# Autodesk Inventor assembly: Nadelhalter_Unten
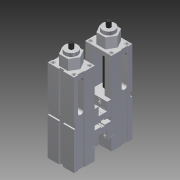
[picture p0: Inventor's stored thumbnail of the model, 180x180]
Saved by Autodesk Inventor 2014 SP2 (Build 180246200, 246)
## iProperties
Created: 2015-06
Part Number: Nadelhalter_Unten
Document SubType Name: Assembly
Designer: e_krauts
Mass: 8692.88 g
Surface Area: 10150.6 cm^2
Volume: 8677.37 cm^3
Density: 1.00179 g/cm^3
Sending System: SolidWorks 2011
Last Author: e_boekem
Author: e_krauts
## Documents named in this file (8)
- C:\Users\e_krauts\AppData\Local\SolidCAM Temporary Files\NADELHALTER_UNTEN\DesignModel.iam
- Z:\VDW-Nachwuchsstiftung Intern\Mitarbeiter Ablage\Steffen Krauth\IVCAM\Nadelhalterung.ipt
- C:\Users\e_krauts\AppData\Local\SolidCAM Temporary Files\NADELHALTER_UNTEN\Schraubstock.iam
- C:\Users\e_krauts\AppData\Local\SolidCAM Temporary Files\NADELHALTER_UNTEN\Backe20x40.ipt
- C:\Users\e_krauts\AppData\Local\SolidCAM Temporary Files\NADELHALTER_UNTEN\Unterteil.ipt
- C:\Users\e_krauts\AppData\Local\SolidCAM Temporary Files\NADELHALTER_UNTEN\Backe 40 x 20 ohne.ipt
- C:\Users\e_krauts\AppData\Local\SolidCAM Temporary Files\NADELHALTER_UNTEN\Spindel.ipt
- C:\Users\e_krauts\AppData\Local\SolidCAM Temporary Files\NADELHALTER_UNTEN\Nadelhalterung-Unterteil_01.ipt
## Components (6 placed, 6 different names)
1. Backe20x40:1 — Passend:2, Fluchtend:1, Fluchtend:3
2. Unterteil:1 — Passend:1, Passend:2, Passend:4, Passend:5, Fluchtend:1
3. Backe 40 x 20 ohne:1 — Passend:3, Passend:4, Fluchtend:4, Fluchtend:5, Passend:6, Passend:7
4. Spindel:2 — Passend:1, Passend:3, Passend:5
5. Schraubstock:1 [sub-assembly] — Fluchtend:3, Fluchtend:4
6. Nadelhalterung-Unterteil_01:1 — Fluchtend:5, Passend:6, Passend:7
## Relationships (11: Mate 7, Flush 4)
- Passend:1 [Mate]: Unterteil:1 ↔ Spindel:2
- Passend:2 [Mate]: Backe20x40:1 ↔ Unterteil:1
- Passend:3 [Mate]: Backe 40 x 20 ohne:1 ↔ Spindel:2
- Passend:4 [Mate]: Unterteil:1 ↔ Backe 40 x 20 ohne:1
- Passend:5 [Mate]: Unterteil:1 ↔ Spindel:2
- Fluchtend:1 [Flush]: Backe20x40:1 ↔ Unterteil:1
- Fluchtend:3 [Flush]: Backe20x40:1 ↔ Schraubstock:1
- Fluchtend:4 [Flush]: Backe 40 x 20 ohne:1 ↔ Schraubstock:1
- Fluchtend:5 [Flush]: Backe 40 x 20 ohne:1 ↔ Nadelhalterung-Unterteil_01:1
- Passend:6 [Mate]: Backe 40 x 20 ohne:1 ↔ Nadelhalterung-Unterteil_01:1
- Passend:7 [Mate]: Backe 40 x 20 ohne:1 ↔ Nadelhalterung-Unterteil_01:1
